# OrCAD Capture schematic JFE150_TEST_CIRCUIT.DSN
size A; title: Ultra-Low Noise, Low-Input Bias Current, Discrete,; rev: 1.0; note: Datasheet: SLPS732 EVM: N/A
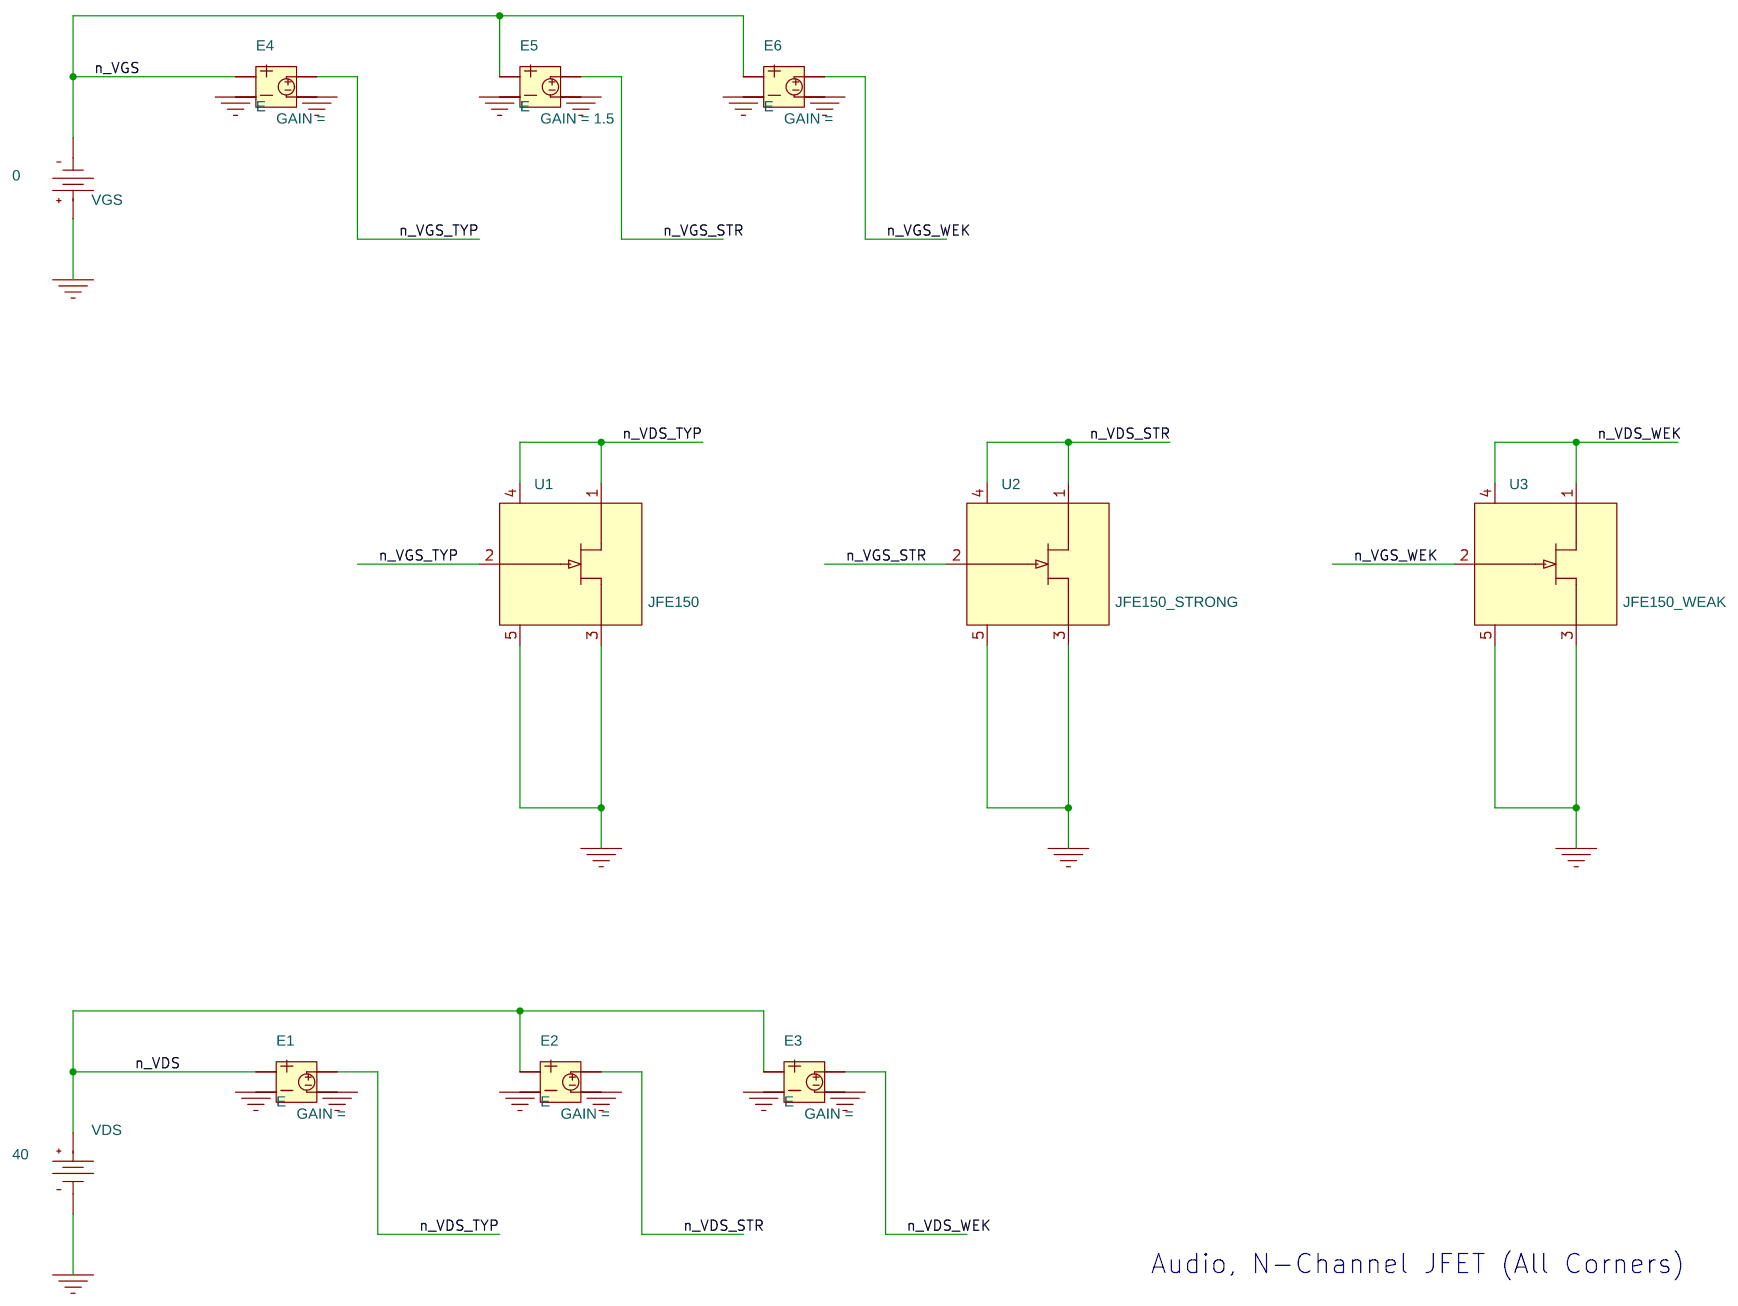
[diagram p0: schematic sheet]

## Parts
E1  E
E2  E
E3  E
E4  E
E5  E
E6  E
U1  JFE150
U2  JFE150_STRONG
U3  JFE150_WEAK
VDS  VDC
VGS  VDC

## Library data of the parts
E1-E4 E6 = E
E5 = E: GAIN: 1.5
U1 = JFE150
U2 = JFE150_STRONG
U3 = JFE150_WEAK
VDS = VDC: AppProp: DC$Voltage$0$-1; DC: 40
VGS = VDC: AppProp: DC$Voltage$0$-1; DC: 0

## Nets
0: E1.2 E1.4 E2.2 E2.4 E3.2 E3.4 E4.2 E4.4 E5.2 E5.4 E6.2 E6.4 U1.3(S) U1.5(VEE) U2.3(S) U2.5(VEE) U3.3(S) U3.5(VEE) VDS.1(-) VGS.0(+)
n_VDS: E1.1 E2.1 E3.1 VDS.0(+)
n_VDS_STR: E2.3 U2.1(D) U2.4(VCC)
n_VDS_TYP: E1.3 U1.1(D) U1.4(VCC)
n_VDS_WEK: E3.3 U3.1(D) U3.4(VCC)
n_VGS: E4.1 E5.1 E6.1 VGS.1(-)
n_VGS_STR: E5.3 U2.2(G)
n_VGS_TYP: E4.3 U1.2(G)
n_VGS_WEK: E6.3 U3.2(G)

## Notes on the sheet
- Audio, N-Channel JFET (All Corners)
